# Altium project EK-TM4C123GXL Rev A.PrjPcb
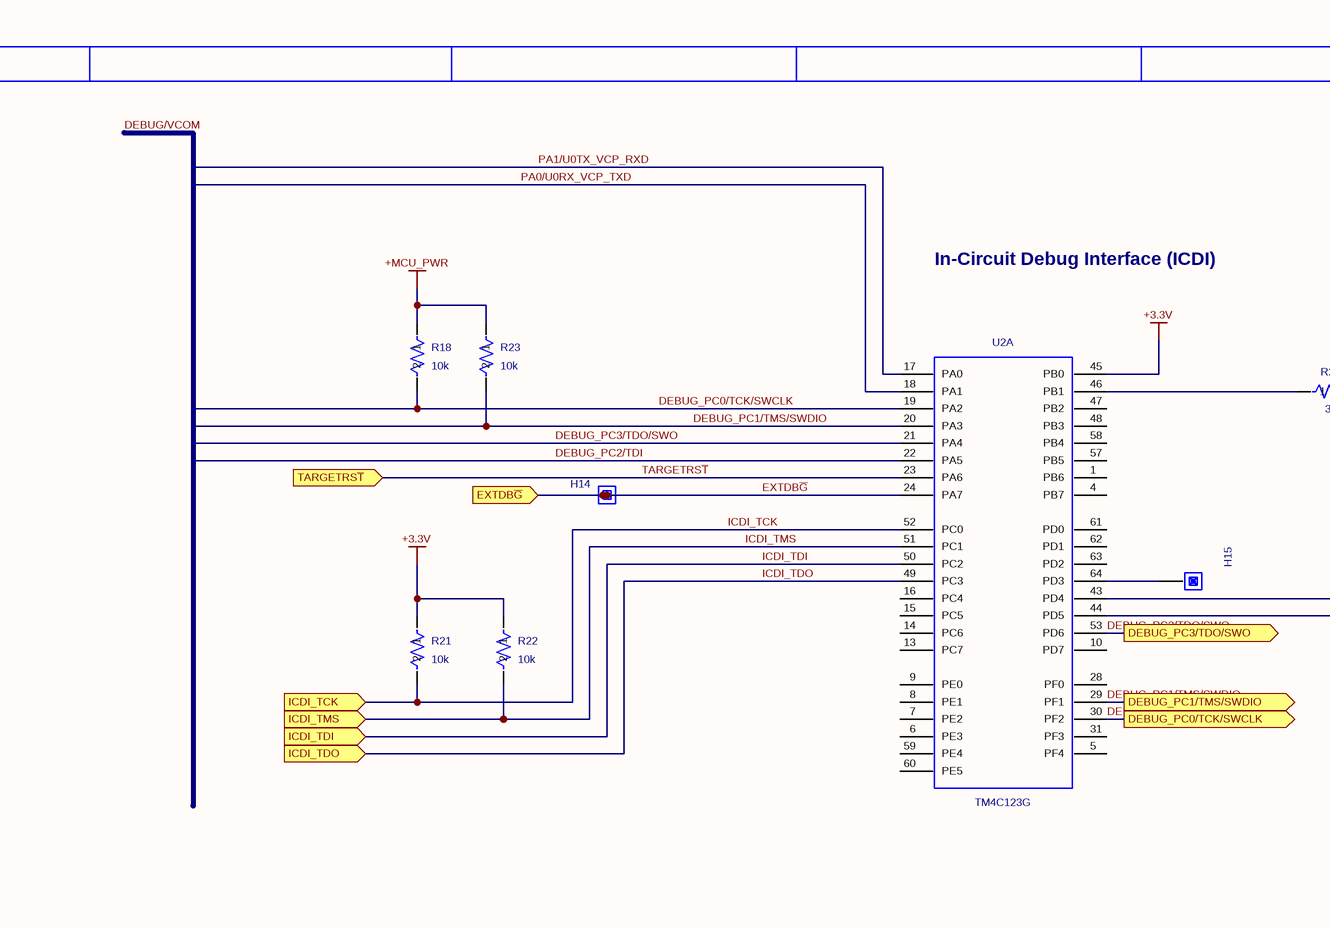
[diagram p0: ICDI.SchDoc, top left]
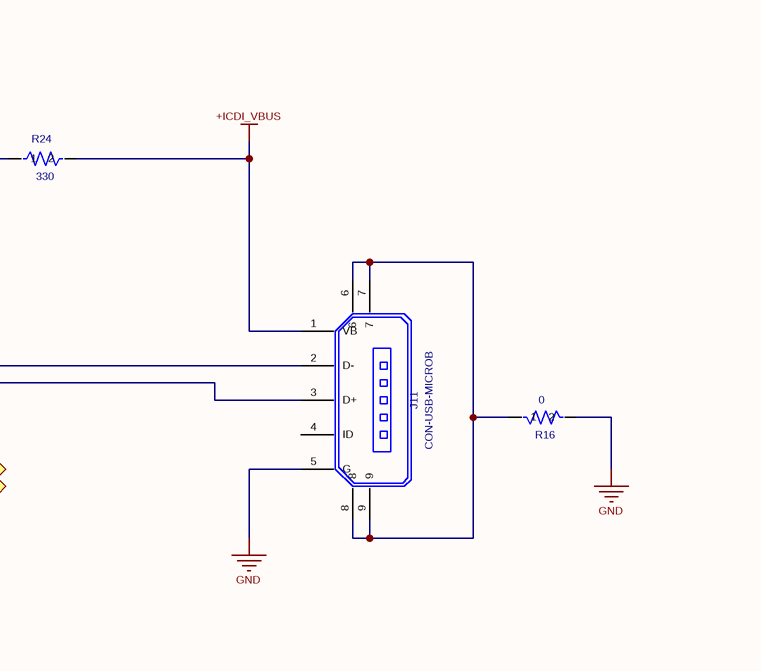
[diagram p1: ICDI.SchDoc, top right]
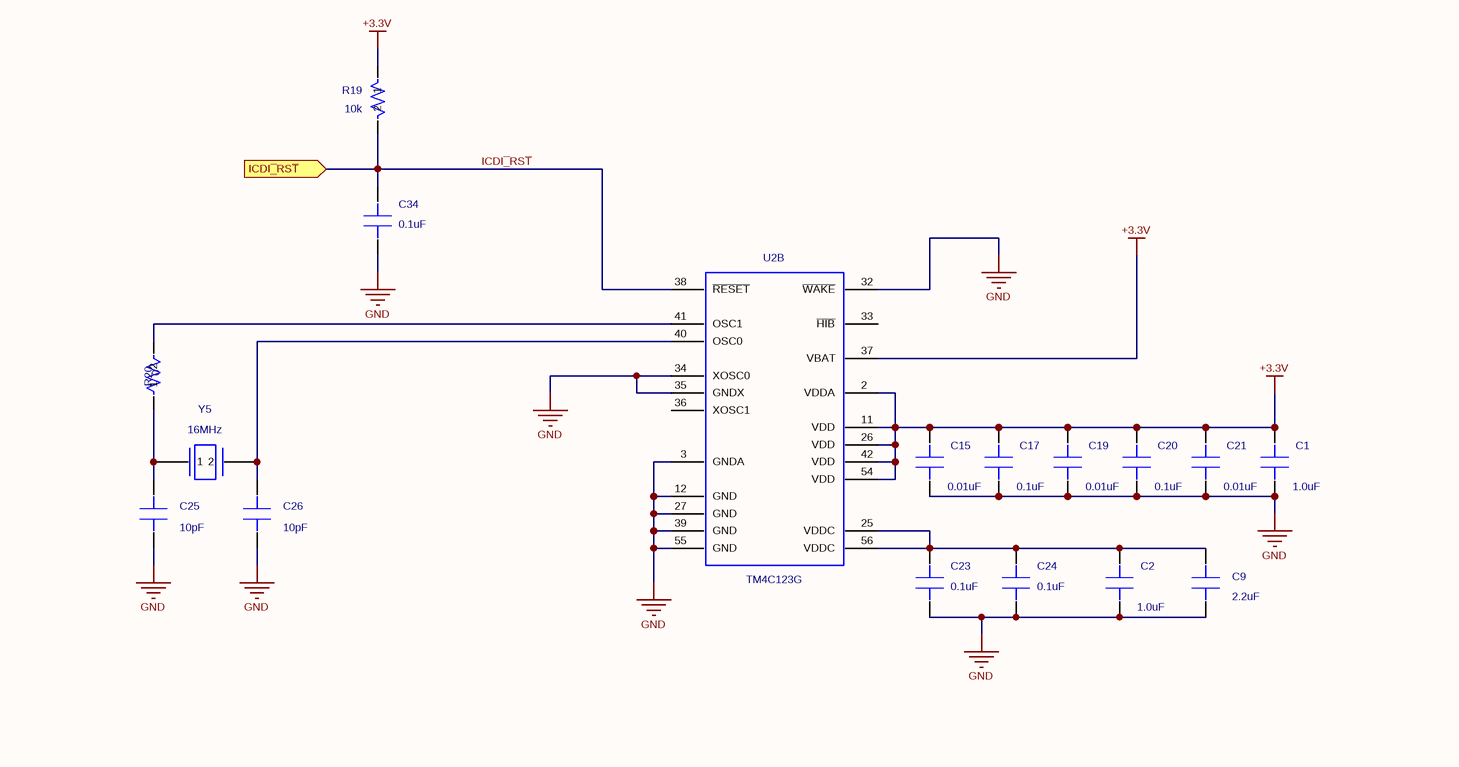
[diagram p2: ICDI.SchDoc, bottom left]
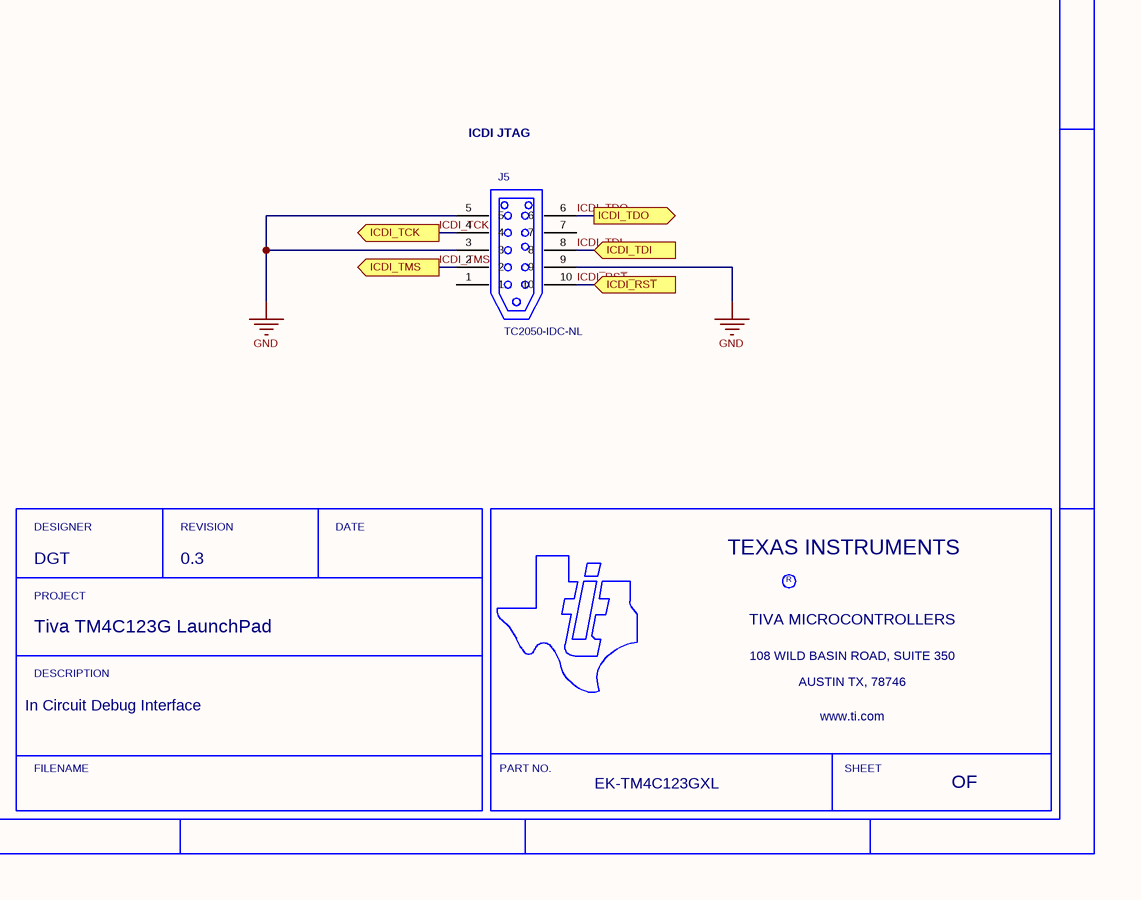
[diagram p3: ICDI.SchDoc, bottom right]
3 sheets, 107 parts. Net scope: flat (ports and power ports of the same name join across sheets).
Board files: EK-TM4C123GXL Rev A_pcb.PcbDoc, PCB4.PcbDoc
Sheets:
  ICDI.SchDoc
  IO.SchDoc
  POWER.SchDoc

## Sheet ICDI.SchDoc
size 431 x 279 mm

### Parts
C1  value 1.0uF  [CAPC0402N]  (hidden comment: CAPC0402)
C2  value 1.0uF  [CAPC0402N]  (hidden comment: CAPC0402)
C9  value 2.2uF  [CAPC0603N]  (hidden comment: CAPC0603)
C15  value 0.01uF  [CAPC0402N]  (hidden comment: CAPC0402)
C17  value 0.1uF  [CAPC0402N]  (hidden comment: CAPC0402)
C19  value 0.01uF  [CAPC0402N]  (hidden comment: CAPC0402)
C20  value 0.1uF  [CAPC0402N]  (hidden comment: CAPC0402)
C21  value 0.01uF  [CAPC0402N]  (hidden comment: CAPC0402)
C23  value 0.1uF  [CAPC0402N]  (hidden comment: CAPC0402)
C24  value 0.1uF  [CAPC0402N]  (hidden comment: CAPC0402)
C25  value 10pF  [CAPC0402N]  (hidden comment: CAPC0402)
C26  value 10pF  [CAPC0402N]  (hidden comment: CAPC0402)
C34  value 0.1uF  [CAPC0402N]  (hidden comment: CAPC0402)
H14  (no value)
H15  (no value)  [PAD70H39]
J5  TC2050-IDC-NL  [TC2050-IDC-NL]
J11  CON-USB-MICROB  [CON-USB-MICRO-S]
R16  value 0  [RESC0603N]  (hidden comment: RESC0603)
R18  value 10k  [RESC0402N]  (hidden comment: RESC0402)
R19  value 10k  [RESC0402N]  (hidden comment: RESC0402)
R20  value 0  [RESC0603N]  (hidden comment: RESC0603)
R21  value 10k  [RESC0402N]  (hidden comment: RESC0402)
R22  value 10k  [RESC0402N]  (hidden comment: RESC0402)
R23  value 10k  [RESC0402N]  (hidden comment: RESC0402)
R24  value 330  [RESC0402N]  (hidden comment: RESC0402)
U2  TM4C123G  [QFP50P1200X1200X160-64N]  (parts A,B of 2)
Y5  value 16MHz  [XTAL-NX5032GA]  (hidden comment: XTAL-NX5032GA)

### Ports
DEBUG_PC0/TCK/SWCLK, DEBUG_PC1/TMS/SWDIO, DEBUG_PC3/TDO/SWO, EXTDB~{G}, ICDI_TCK, ICDI_TCK (out), ICDI_TDI, ICDI_TDI (in), ICDI_TDO, ICDI_TMS, ICDI_TMS (out), ICDI~{_}RS~{T}, ICDI~{_}RS~{T} (in), TARGETRS~{T}

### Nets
+3.3V: C1.1 C15.1 C17.1 C19.1 C20.1 C21.1 R19.1 R21.1 R22.1 U2.2(VDDA) U2.11(VDD) U2.26(VDD) U2.37(VBAT) U2.42(VDD) U2.45(PB0) U2.54(VDD)
+ICDI_VBUS: J11.1(VB) R24.2
+MCU_PWR: R18.1 R23.1
GND: C1.2 C2.2 C9.2 C15.2 C17.2 C19.2 C20.2 C21.2 C23.2 C24.2 C25.2 C26.2 C34.2 J5.3 J5.5 J5.9 J11.5(G) R16.2 U2.3(GNDA) U2.12(GND) U2.27(GND) U2.32(~{WAKE}) U2.34(XOSC0) U2.35(GNDX) U2.39(GND) U2.55(GND)
EXTDB~{G}: H14.1 U2.24(PA7) ; port EXTDB~{G}
TARGETRS~{T}: U2.23(PA6) ; port TARGETRS~{T}
DEBUG_PC0/TCK/SWCLK: R18.2 U2.19(PA2) U2.30(PF2) ; port DEBUG_PC0/TCK/SWCLK
DEBUG_PC1/TMS/SWDIO: R23.2 U2.20(PA3) U2.29(PF1) ; port DEBUG_PC1/TMS/SWDIO
DEBUG_PC2/TDI: U2.22(PA5)
DEBUG_PC3/TDO/SWO: U2.21(PA4) U2.53(PD6) ; port DEBUG_PC3/TDO/SWO
ICDI~{_}RS~{T}: C34.1 J5.10 R19.2 U2.38(~{RESET}) ; port ICDI~{_}RS~{T}
ICDI_TCK: J5.4 R21.2 U2.52(PC0) ; port ICDI_TCK
ICDI_TDI: J5.8 U2.50(PC2) ; port ICDI_TDI
ICDI_TDO: J5.6 U2.49(PC3) ; port ICDI_TDO
ICDI_TMS: J5.2 R22.2 U2.51(PC1) ; port ICDI_TMS
PA0/U0RX_VCP_TXD: U2.18(PA1)
PA1/U0TX_VCP_RXD: U2.17(PA0)
NetC2_1: C2.1 C9.1 C23.1 C24.1 U2.25(VDDC) U2.56(VDDC)
NetC25_1: C25.1 R20.1 Y5.1
NetC26_1: C26.1 U2.40(OSC0) Y5.2
NetH15_1: H15.1 U2.64(PD3)
NetJ11_2: J11.2(D-) U2.43(PD4)
NetJ11_3: J11.3(D+) U2.44(PD5)
NetJ11_6: J11.6 J11.7 J11.8 J11.9 R16.1
NetR20_2: R20.2 U2.41(OSC1)
NetR24_1: R24.1 U2.46(PB1)

Not connected (* = marked no-connect by the designer): J5 1 7; J11 4(ID); U2 1(PB6) 4(PB7) 5(PF4) 6(PE3) 7(PE2) 8(PE1) 9(PE0) 10(PD7) 13(PC7) 14(PC6) 15(PC5) 16(PC4) 28(PF0) 31(PF3) 33(~{HIB}) 36(XOSC1) 47(PB2) 48(PB3) 57(PB5) 58(PB4) 59(PE4) 60(PE5) 61(PD0) 62(PD1) 63(PD2)

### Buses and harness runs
bus DEBUG/VCOM

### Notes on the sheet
- In-Circuit Debug Interface (ICDI)
- ICDI JTAG
- DGT
- DESIGNER
- 0.3
- REVISION
- DATE
- R
- TEXAS INSTRUMENTS
- Tiva TM4C123G LaunchPad
- PROJECT
- TIVA MICROCONTROLLERS
- 108 WILD BASIN ROAD, SUITE 350
- In Circuit Debug Interface
- DESCRIPTION
- www.ti.com
- AUSTIN TX, 78746
- FILENAME
- PART NO.
- EK-TM4C123GXL
- SHEET
- OF

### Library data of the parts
C1 C2 = CAPC0402: SURFACE MOUNT CAPACITOR 0402; Manufacturer #1: IPC SM-782 STD.; Sim.Analog.Order: Model$; GNUM: G10-C0402-C105-GBB
C9 = CAPC0603: SURFACE MOUNT CAPACITOR 0.031 X 0.061 INCHES; Manufacturer #1: IPC SM-782 STD.; Sim.Analog.Order: Model$; GNUM: G10-C0603-C225-HBB
C15 C19 C21 = CAPC0402: SURFACE MOUNT CAPACITOR 0402; Manufacturer #1: IPC SM-782 STD.; Sim.Analog.Order: Model$; GNUM: G10-C0402-C103-BBA
C17 C20 C23 C24 = CAPC0402: SURFACE MOUNT CAPACITOR 0402; Manufacturer #1: IPC SM-782 STD.; Sim.Analog.Order: Model$; GNUM: G10-C0402-C104-HBA
C25 C26 = CAPC0402: SURFACE MOUNT CAPACITOR 0402; Manufacturer #1: IPC SM-782 STD.; Sim.Analog.Order: Model$; GNUM: C10-C0402-C100-AAC
C34 = CAPC0402: OMIT; Manufacturer #1: IPC SM-782 STD.; Sim.Analog.Order: Model$; GNUM: G10-C0402-C104-HBA
H14 = HDR-INLINE: POPOP: OMIT
H15 = HDR-ENDLINE: POPOP: OMIT
J5 = TC2050-IDC-NL: POPOP: OMIT
J11 = CON-USB-MICROB: Connector, USB micro AB Receptacle SMT; Part Number: ZX62-B-5PA; Manufacturer #1: Hirose; GNUM: G20-USBM-SMMB-AAA
R16 = RESC0603: GNUM: G11-R0603-R000-AAA
R18 R19 R21-R23 = RESC0402: Resistor,Chip;1.00mm L X 0.5mm W X 0.35mm H; Manufacturer #1: Generic; Part Number: TBD; Also Known As: 0402; PCBL.Component: CHP;RESC;1500;1700;150;400;700;950;600; PCBL.Process: F;N;50;50;200;100;200;250;350;-50;0; Tolerance: 5%; GNUM: G11-R0402-1002-AAA
R20 = RESC0603: Resistor,Chip;1.60mm L X 0.83mm W X 0.60mm H; Manufacturer #1: Generic; Part Number: TBD; GNUM: G11-R0603-R000-AAA; Also Known As: 0603; Geometry.Height: 0.6mm; PCBL.Component: CHP;RESC;1500;1700;150;400;700;950;600; PCBL.Process: F;N;50;50;200;100;200;250;350;-50;0
R24 = RESC0402: Resistor,Chip;1.00mm L X 0.5mm W X 0.35mm H; Manufacturer #1: Generic; Part Number: TBD; Also Known As: 0402; PCBL.Component: CHP;RESC;1500;1700;150;400;700;950;600; PCBL.Process: F;N;50;50;200;100;200;250;350;-50;0; Tolerance: 5%; GNUM: G11-R0402-3300-AAA; POPOP: OMIT
U2 = TM4C123G: GNUM: G50-QFP64-F120-EGC
Y5 = XTAL-NX5032GA: Crystal, 16.00MHz 5.0x3.2mm SMT; Manufacturer #1: tbd; Part Number: NX5032GA-16.000000MHZ; GNUM: G15-5X3P2-1606-AAA

## Sheet IO.SchDoc
size 431 x 279 mm
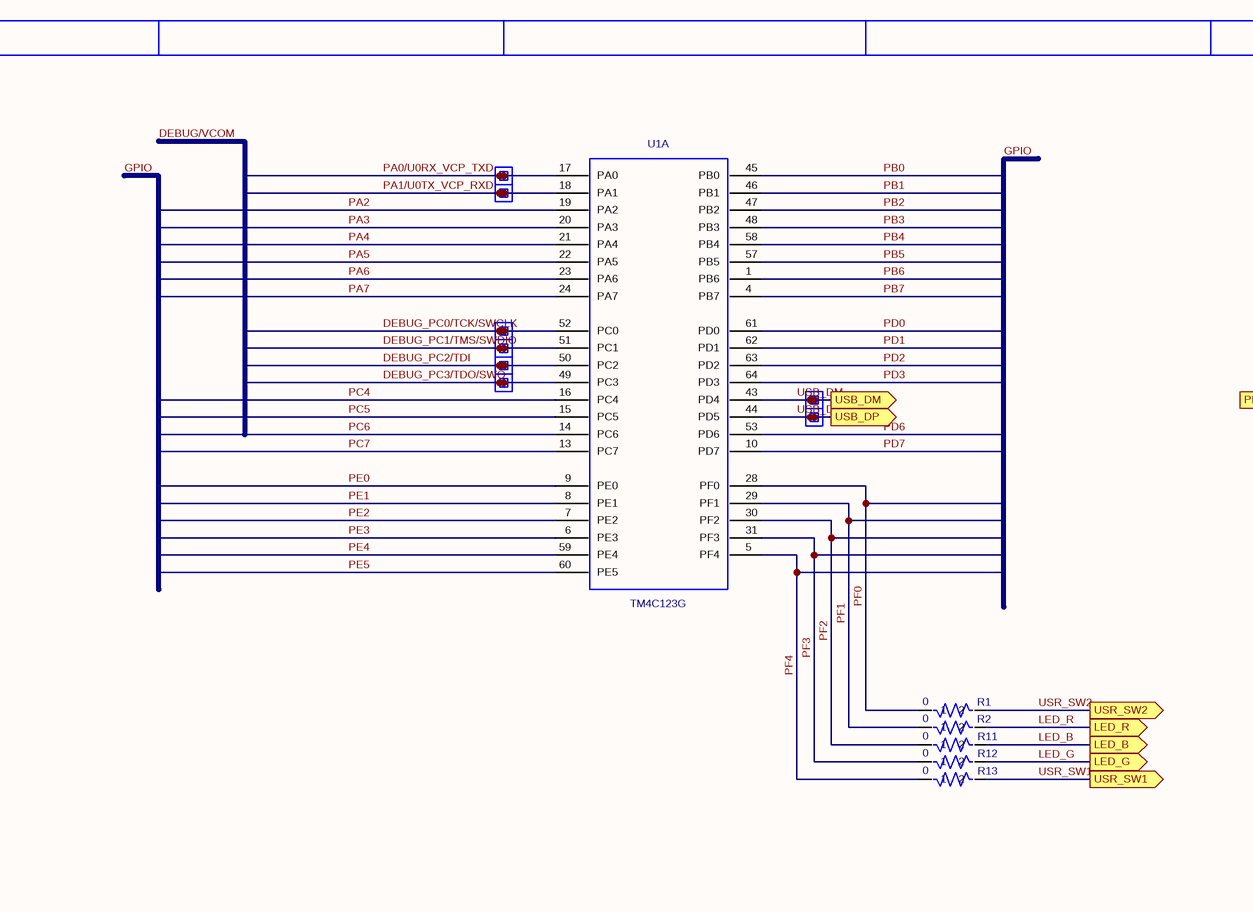
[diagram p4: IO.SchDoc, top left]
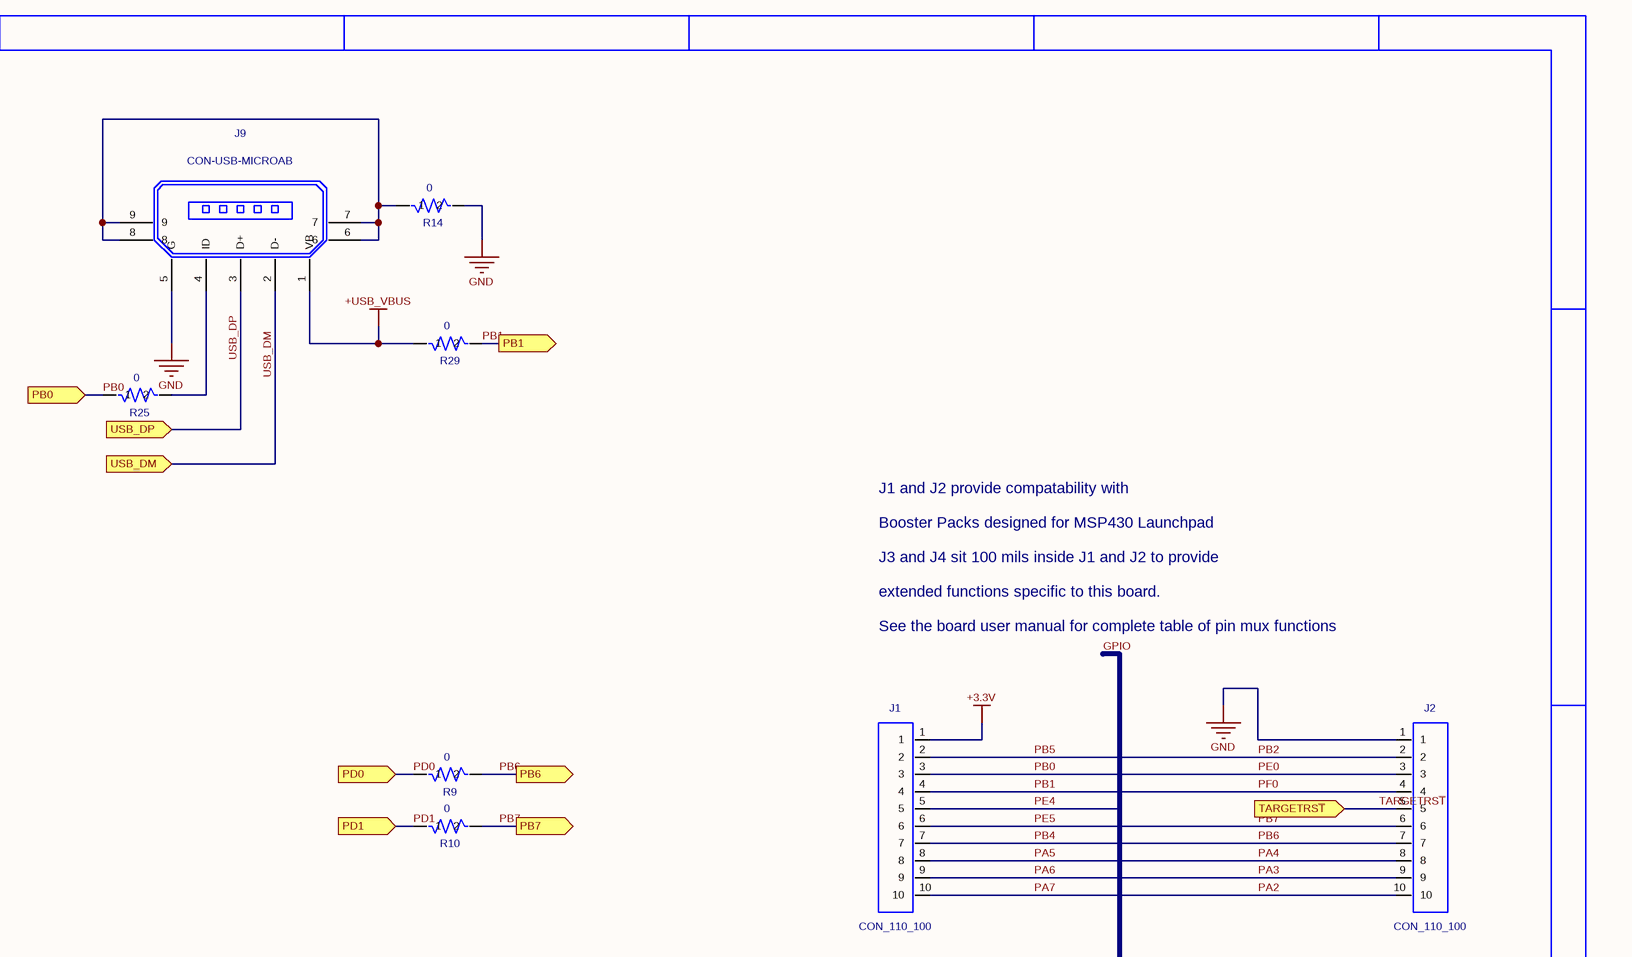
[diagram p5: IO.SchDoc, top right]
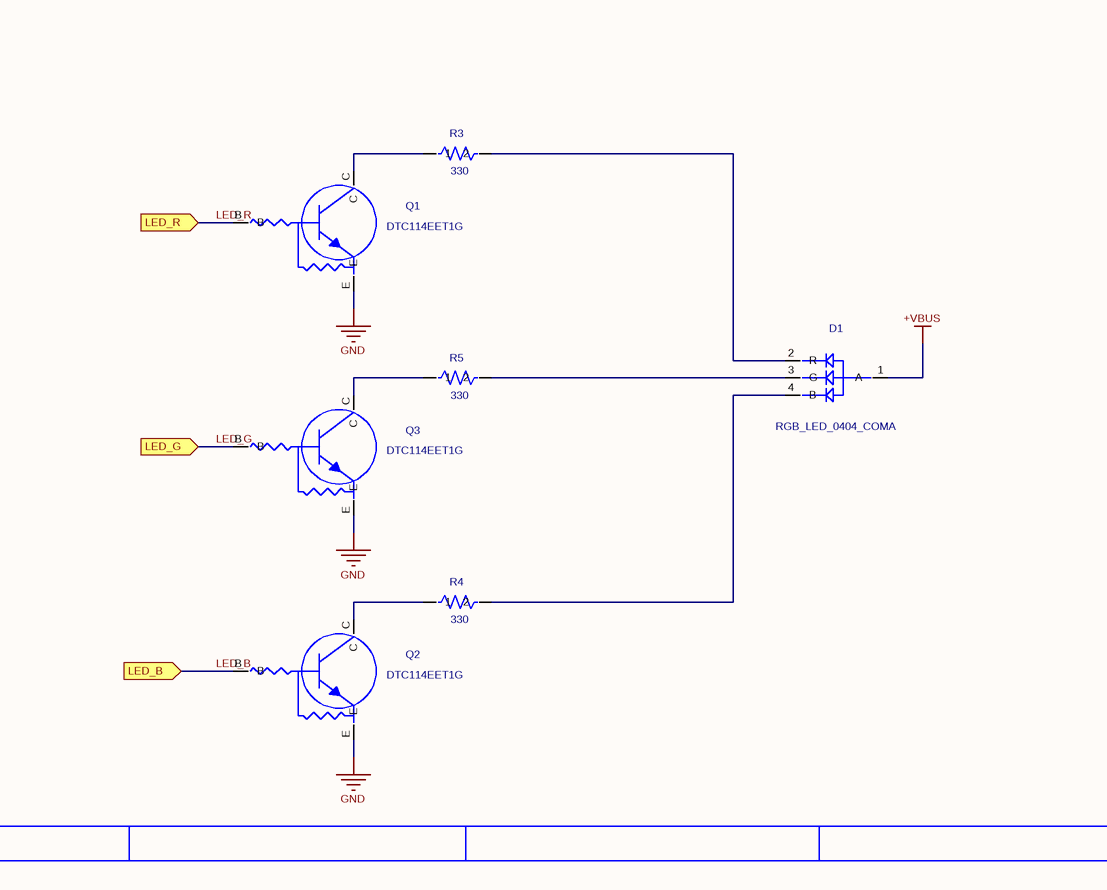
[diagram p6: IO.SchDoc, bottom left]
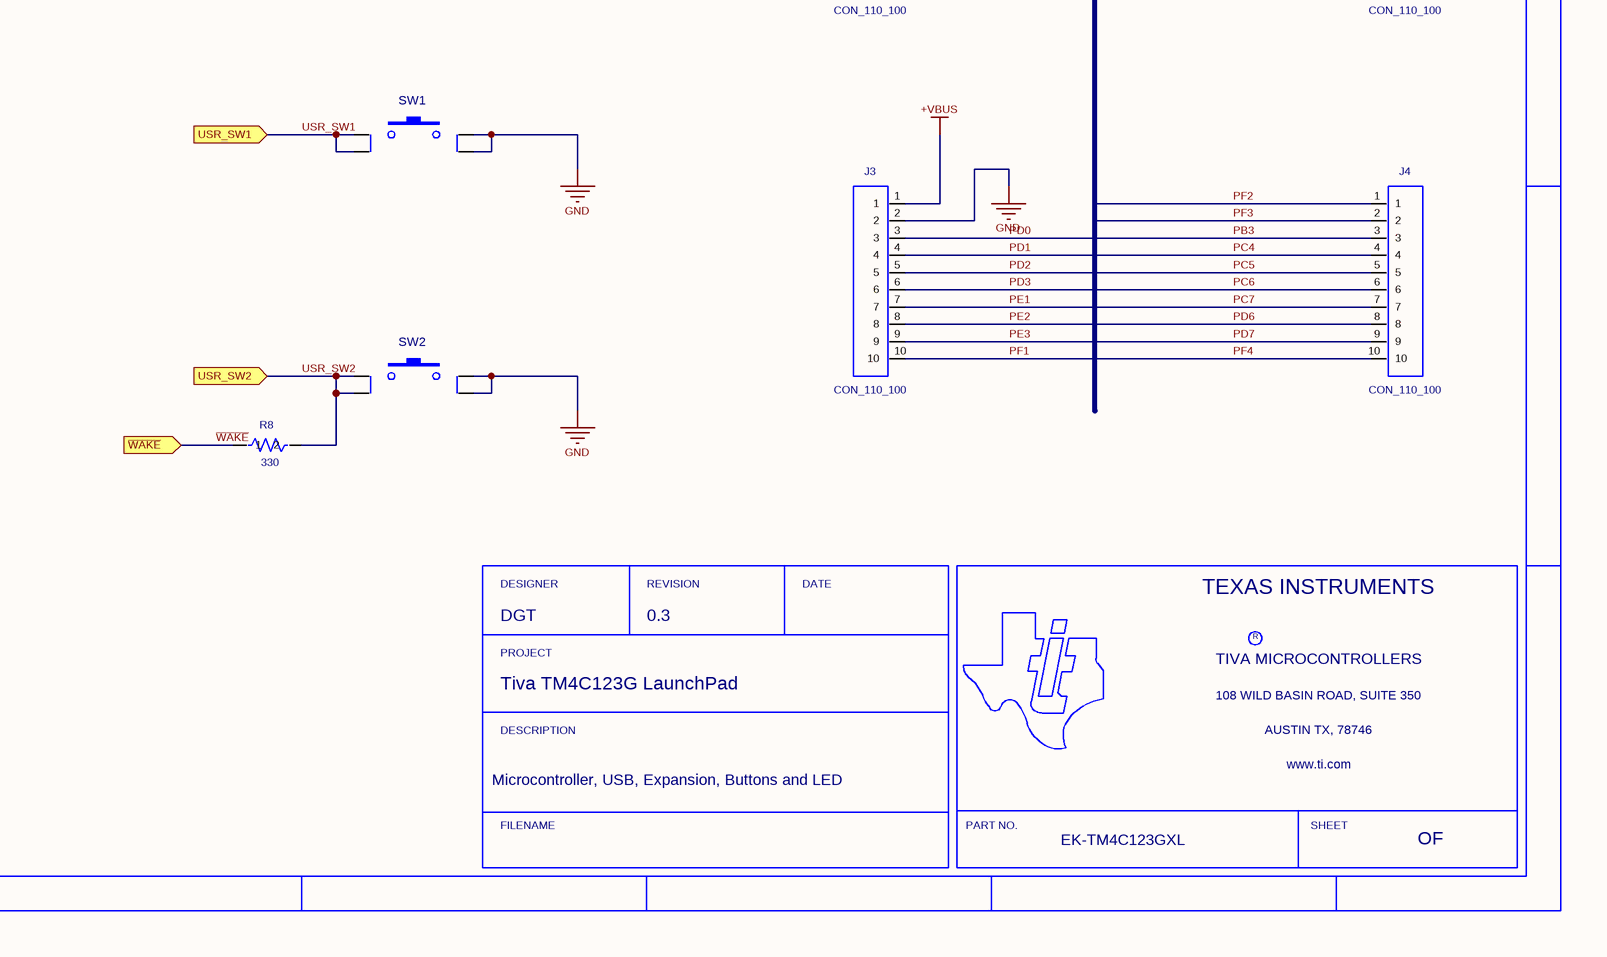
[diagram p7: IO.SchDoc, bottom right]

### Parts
D1  RGB_LED_0404_COMA  [0404_QUAD]
H3  (no value)
H4  (no value)
H5  (no value)
H6  (no value)
H7  (no value)
H8  (no value)
H9  (no value)
H91  (no value)
J1  CON_110_100  [TSW-110-100]
J2  CON_110_100  [TSW-110-100]
J3  CON_110_100  [TSW-110-100]
J4  CON_110_100  [TSW-110-100]
J9  CON-USB-MICROAB  [CON-USB-MICRO-S]
Q1  DTC114EET1G  [SC-75/SOT-416]
Q2  DTC114EET1G  [SC-75/SOT-416]
Q3  DTC114EET1G  [SC-75/SOT-416]
R1  value 0  [RESC0603N]  (hidden comment: RESC0603)
R2  value 0  [RESC0603N]  (hidden comment: RESC0603)
R3  value 330  [RESC0402N]  (hidden comment: RESC0402)
R4  value 330  [RESC0402N]  (hidden comment: RESC0402)
R5  value 330  [RESC0402N]  (hidden comment: RESC0402)
R8  value 330  [RESC0402N]  (hidden comment: RESC0402)
R9  value 0  [RESC0603N]  (hidden comment: RESC0603)
R10  value 0  [RESC0603N]  (hidden comment: RESC0603)
R11  value 0  [RESC0603N]  (hidden comment: RESC0603)
R12  value 0  [RESC0603N]  (hidden comment: RESC0603)
R13  value 0  [RESC0603N]  (hidden comment: RESC0603)
R14  value 0  [RESC0603N]  (hidden comment: RESC0603)
R25  value 0  [RESC0603N]  (hidden comment: RESC0603)
R29  value 0  [RESC0603N]  (hidden comment: RESC0603)
SW1  SW-EVQQ2  [SW-EVQQ2]  (value not drawn)
SW2  SW-EVQQ2  [SW-EVQQ2]  (value not drawn)
U1  TM4C123G  [QFP50P1200X1200X160-64N]  (part A of 2)

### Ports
LED_B, LED_G, LED_R, PB0, PB1, PB6, PB7, PD0, PD1, TARGETRS~{T}, USB_DM, USB_DP, USR_SW1, USR_SW2, ~{WAKE}

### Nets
+3.3V: J1.1
+USB_VBUS: J9.1(VB) R29.1
+VBUS: D1.1(A) J3.1
GND: J2.1 J3.2 J9.5(G) Q1.E Q2.E Q3.E R14.2 SW1.2 SW1.4 SW2.2 SW2.4
TARGETRS~{T}: J2.5 ; port TARGETRS~{T}
~{WAKE}: R8.1 ; port ~{WAKE}
DEBUG_PC0/TCK/SWCLK: H91.1 U1.52(PC0)
DEBUG_PC1/TMS/SWDIO: H3.1 U1.51(PC1)
DEBUG_PC2/TDI: H4.1 U1.50(PC2)
DEBUG_PC3/TDO/SWO: H5.1 U1.49(PC3)
LED_B: Q2.B R11.2 ; port LED_B
LED_G: Q3.B R12.2 ; port LED_G
LED_R: Q1.B R2.2 ; port LED_R
PA0/U0RX_VCP_TXD: H6.1 U1.17(PA0)
PA1/U0TX_VCP_RXD: H7.1 U1.18(PA1)
PA2: J1.10 J2.10 U1.19(PA2) U1.24(PA7)  [also labelled PA7]
PA3: J1.9 J2.9 U1.20(PA3) U1.23(PA6)  [also labelled PA6]
PA4: J1.8 J2.8 U1.21(PA4) U1.22(PA5)  [also labelled PA5]
PB0: J1.3 J2.3 R25.1 U1.9(PE0) U1.45(PB0) ; port PB0  [also labelled PE0]
PB1: J1.4 J2.4 R1.1 R29.2 U1.28(PF0) U1.46(PB1) ; port PB1  [also labelled PF0]
PB2: J1.2 J2.2 U1.47(PB2) U1.57(PB5)  [also labelled PB5]
PB3: J3.3 J4.3 R9.1 U1.48(PB3) U1.61(PD0) ; port PD0  [also labelled PD0]
PB4: J1.7 J2.7 R9.2 U1.1(PB6) U1.58(PB4) ; port PB6  [also labelled PB6]
PB7: J1.6 J2.6 R10.2 U1.4(PB7) U1.60(PE5) ; port PB7  [also labelled PE5]
PC4: J3.4 J4.4 R10.1 U1.16(PC4) U1.62(PD1) ; port PD1  [also labelled PD1]
PC5: J3.5 J4.5 U1.15(PC5) U1.63(PD2)  [also labelled PD2]
PC6: J3.6 J4.6 U1.14(PC6) U1.64(PD3)  [also labelled PD3]
PC7: J3.7 J4.7 U1.8(PE1) U1.13(PC7)  [also labelled PE1]
PD6: J3.8 J4.8 U1.7(PE2) U1.53(PD6)  [also labelled PE2]
PD7: J3.9 J4.9 U1.6(PE3) U1.10(PD7)  [also labelled PE3]
PE4: J1.5 U1.59(PE4)
PF1: J3.10 J4.10 R2.1 R13.1 U1.5(PF4) U1.29(PF1)  [also labelled PF4]
PF2: J4.1 R11.1 U1.30(PF2)
PF3: J4.2 R12.1 U1.31(PF3)
USB_DM: H8.1 J9.2(D-) U1.43(PD4) ; port USB_DM
USB_DP: H9.1 J9.3(D+) U1.44(PD5) ; port USB_DP
USR_SW1: R13.2 SW1.1 SW1.3 ; port USR_SW1
USR_SW2: R1.2 R8.2 SW2.1 SW2.3 ; port USR_SW2
NetD1_2: D1.2(R) R3.2
NetD1_3: D1.3(G) R5.2
NetD1_4: D1.4(B) R4.2
NetJ9_4: J9.4(ID) R25.2
NetJ9_6: J9.6 J9.7 J9.8 J9.9 R14.1
NetQ1_C: Q1.C R3.1
NetQ2_C: Q2.C R4.1
NetQ3_C: Q3.C R5.1

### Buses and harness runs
bus DEBUG/VCOM
bus GPIO

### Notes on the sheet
- J1 and J2 provide compatability with
- Booster Packs designed for MSP430 Launchpad
- J3 and J4 sit 100 mils inside J1 and J2 to provide
- extended functions specific to this board.
- See the board user manual for complete table of pin mux functions
- DGT
- DESIGNER
- 0.3
- REVISION
- DATE
- R
- TEXAS INSTRUMENTS
- Tiva TM4C123G LaunchPad
- PROJECT
- 108 WILD BASIN ROAD, SUITE 350
- TIVA MICROCONTROLLERS
- Microcontroller, USB, Expansion, Buttons and LED
- DESCRIPTION
- www.ti.com
- AUSTIN TX, 78746
- FILENAME
- PART NO.
- EK-TM4C123GXL
- SHEET
- OF

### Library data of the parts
D1 = RGB_LED_0404_COMA: GNUM: G14-D0404-RGB3-AAA
H3-H9 H91 = HDR-INLINE: POPOP: OMIT
J1 J3 = CON_110_100: PIN1_X: 0.3; PIN1_Y: 1.4; Geometry.Height: 50.00mil; GNUM: G22-THSTK-2X10-BAC
J2 = CON_110_100: PIN1_X: 2.1; PIN1_Y: 1.4; Geometry.Height: 50.00mil; GNUM: G22-SMHOR-210P-BAB
J4 = CON_110_100: PIN1_X: 0.3; PIN1_Y: 1.4; Geometry.Height: 50.00mil; GNUM: G22-SMHOR-210P-BAB
J9 = CON-USB-MICROAB: Connector, USB micro AB Receptacle SMT; Part Number: ZX62-AB-5PA; Manufacturer #1: Hirose; GNUM: G20-USBU-SMAB-AAA
Q1-Q3 = DTC114EET1G: GENERAL PURPOSE NPN SILICON TRANSISTOR; Manufacturer #1: Diodes Inc; GNUM: G52-SC700-NPNB-AAA
R1 R2 R9-R14 = RESC0603: GNUM: G11-R0603-R000-AAA
R3-R5 R8 = RESC0402: Resistor,Chip;1.00mm L X 0.5mm W X 0.35mm H; Manufacturer #1: Generic; Part Number: TBD; Also Known As: 0402; PCBL.Component: CHP;RESC;1500;1700;150;400;700;950;600; PCBL.Process: F;N;50;50;200;100;200;250;350;-50;0; Tolerance: 5%; GNUM: G11-R0402-3300-AAA
R25 R29 = RESC0603: GNUM: G11-R0603-R000-AAA; POPOP: OMIT
SW1 SW2 = SW-EVQQ2: Switch, Tact 6mm SMT, 50gf; Manufacturer #1: Panasonic; Part Number: EVQ-Q2B02W; GNUM: G21-4P6MM-B3S1-AAA
U1 = TM4C123G: GNUM: G50-QFP64-F120-EGC

## Sheet POWER.SchDoc
size 431 x 279 mm
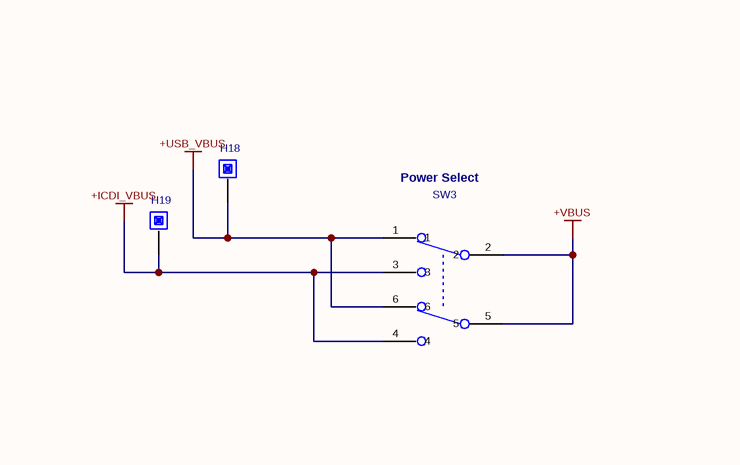
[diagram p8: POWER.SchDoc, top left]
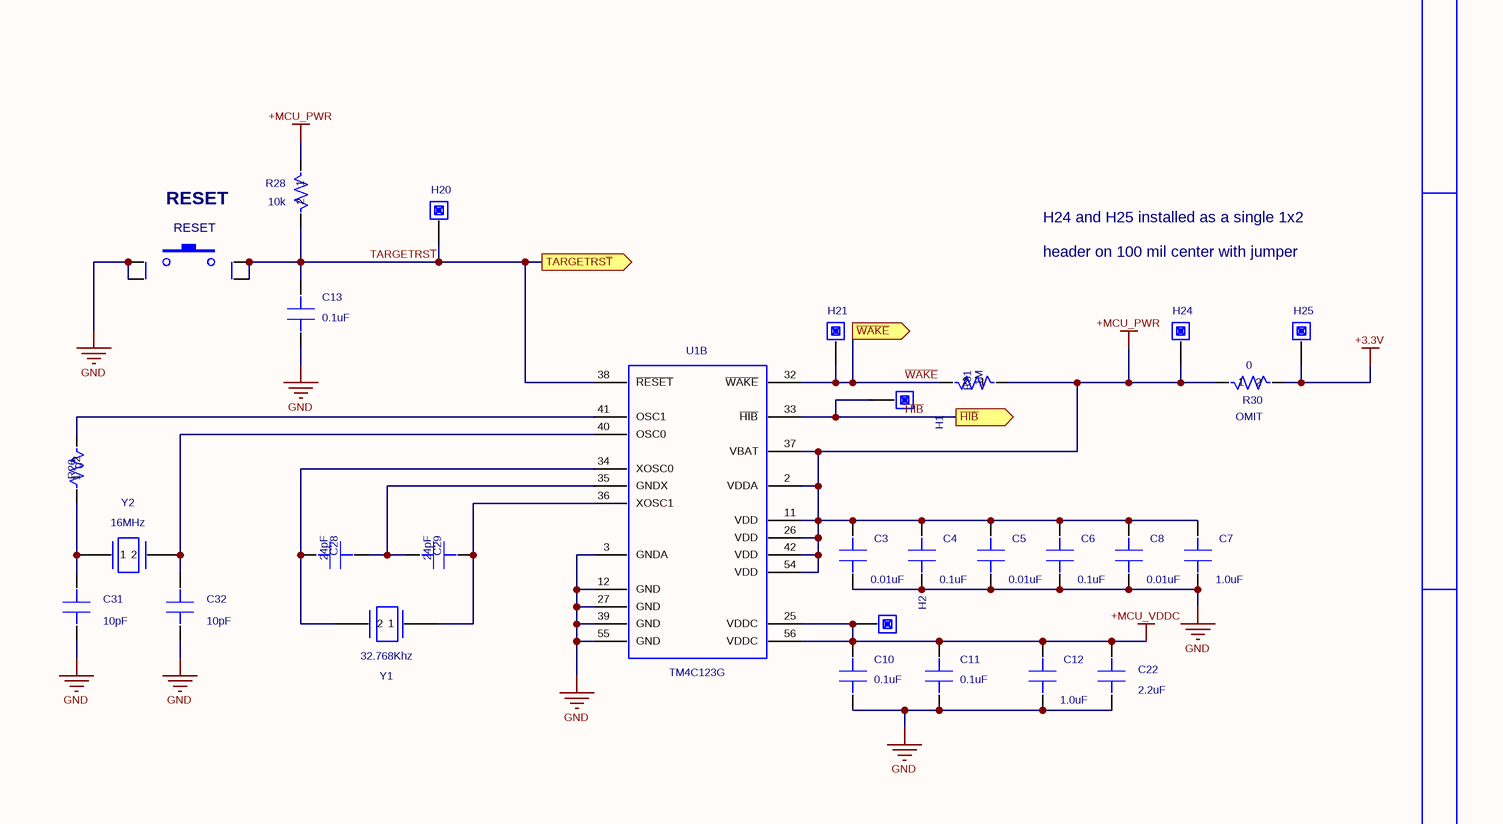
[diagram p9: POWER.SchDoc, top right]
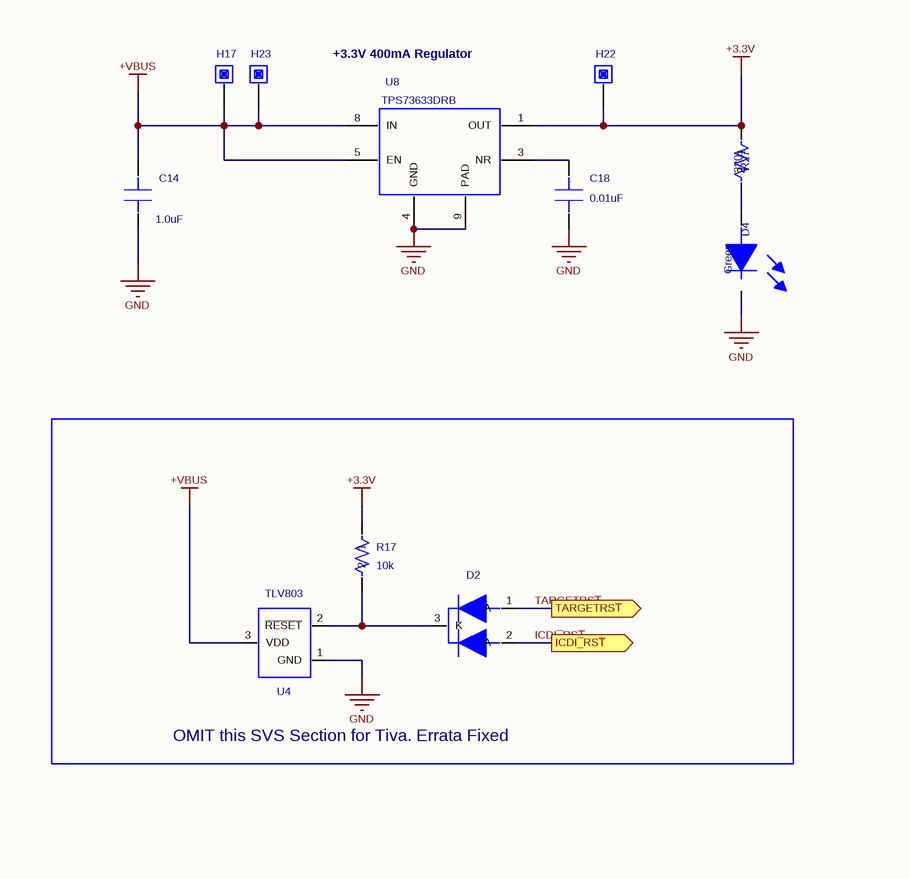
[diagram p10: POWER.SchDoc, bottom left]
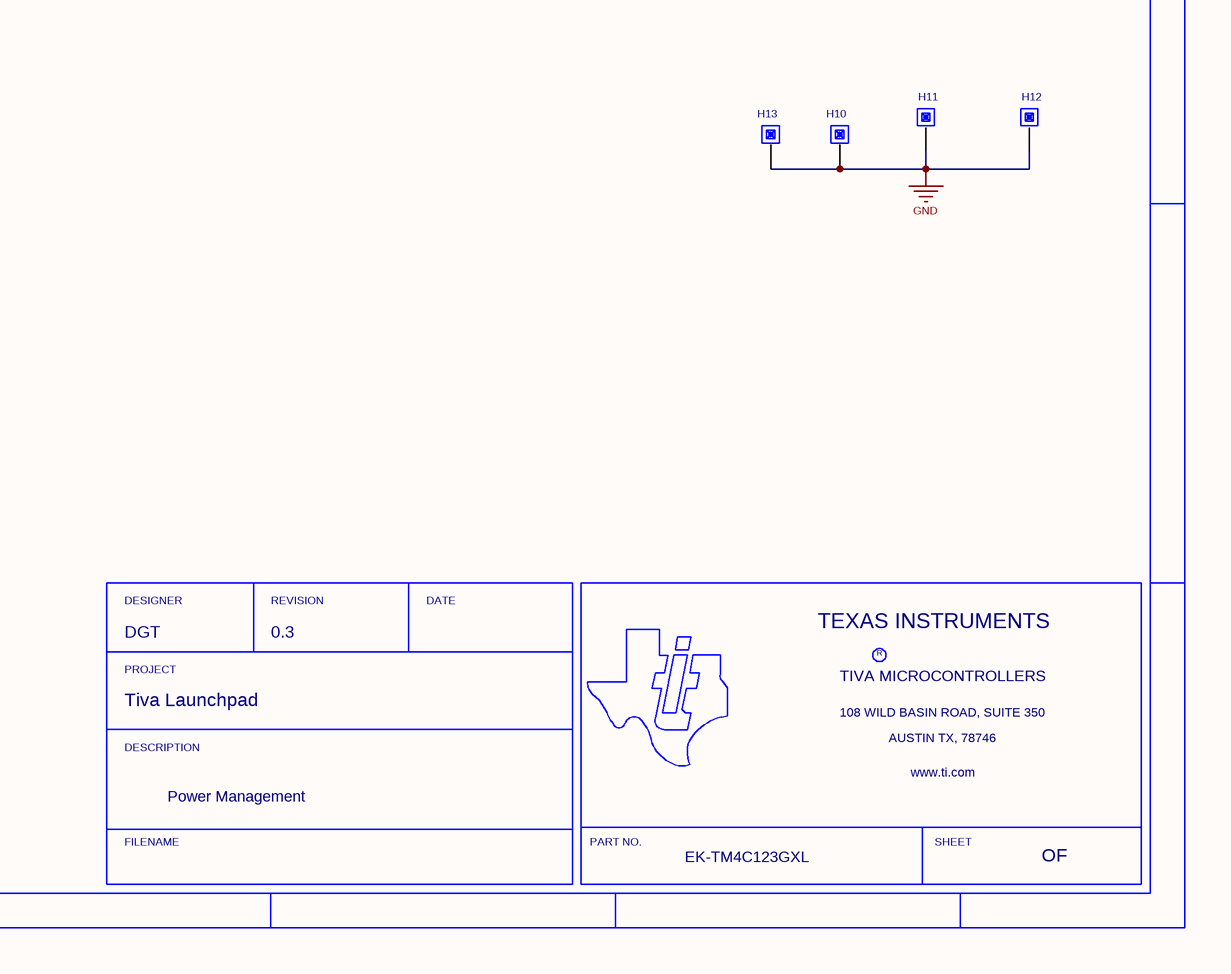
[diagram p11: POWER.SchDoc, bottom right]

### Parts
C3  value 0.01uF  [CAPC0402N]  (hidden comment: CAPC0402)
C4  value 0.1uF  [CAPC0402N]  (hidden comment: CAPC0402)
C5  value 0.01uF  [CAPC0402N]  (hidden comment: CAPC0402)
C6  value 0.1uF  [CAPC0402N]  (hidden comment: CAPC0402)
C7  value 1.0uF  [CAPC0402N]  (hidden comment: CAPC0402)
C8  value 0.01uF  [CAPC0402N]  (hidden comment: CAPC0402)
C10  value 0.1uF  [CAPC0402N]  (hidden comment: CAPC0402)
C11  value 0.1uF  [CAPC0402N]  (hidden comment: CAPC0402)
C12  value 1.0uF  [CAPC0402N]  (hidden comment: CAPC0402)
C13  value 0.1uF  [CAPC0402N]  (hidden comment: CAPC0402)
C14  value 1.0uF  [CAPC0402N]  (hidden comment: CAPC0402)
C18  value 0.01uF  [CAPC0402N]  (hidden comment: CAPC0402)
C22  value 2.2uF  [CAPC0603N]  (hidden comment: CAPC0603)
C28  value 24pF  [CAPC0402N]  (hidden comment: CAPC0402)
C29  value 24pF  [CAPC0402N]  (hidden comment: CAPC0402)
C31  value 10pF  [CAPC0402N]  (hidden comment: CAPC0402)
C32  value 10pF  [CAPC0402N]  (hidden comment: CAPC0402)
D2  DIO_BAT54_CC  [SC70-3]  (value not drawn)
D4  value Green  [DIOC0805N]  (hidden comment: LED-0805)
H1  (no value)  [PAD70H39]
H2  (no value)  [PAD70H39]
H10  (no value)  [PAD70H39]
H11  (no value)  [PAD70H39]
H12  (no value)  [PAD70H39]
H13  (no value)  [PAD70H39]
H17  (no value)  [PAD70H39]
H18  (no value)  [PAD70H39]
H19  (no value)  [PAD70H39]
H20  (no value)  [PAD70H39]
H21  (no value)  [PAD70H39]
H22  (no value)  [PAD70H39]
H23  (no value)  [PAD70H39]
H24  (no value)  [PAD70H39]
H25  (no value)  [PAD70H39]
R17  value 10k  [RESC0402N]  (hidden comment: RESC0402)
R26  value 0  [RESC0603N]  (hidden comment: RESC0603)
R27  value 330  [RESC0402N]  (hidden comment: RESC0402)
R28  value 10k  [RESC0402N]  (hidden comment: RESC0402)
R30  OMIT  value 0  [RESC0603N]
R31  value 1M  [RESC0402N]  (hidden comment: RESC0402)
RESET  SW-EVQQ2  [SW-EVQQ2]  (value not drawn)
SW3  SW_DPDT  [SW_JS202011SCQN]  (value not drawn)
U1  TM4C123G  [QFP50P1200X1200X160-64N]  (part B of 2)
U4  TLV803  [SOT23]
U8  TPS73633DRB  [TI-DRB-SON8]
Y1  value 32.768Khz  [XTAL-AB26TR]  (hidden comment: XTAL-NX5032GA)
Y2  value 16MHz  [XTAL-NX5032GA]  (hidden comment: XTAL-NX5032GA)

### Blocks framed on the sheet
OMIT this SVS Section for Tiva. Errata Fixed: D2 R17 U4

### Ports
ICDI~{_}RS~{T}, TARGETRS~{T}, ~{HIB}, ~{WAKE}

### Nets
+3.3V: H22.1 H25.1 R17.1 R27.1 R30.2 U8.1(OUT)
+ICDI_VBUS: H19.1 SW3.3 SW3.4
+MCU_PWR: C3.1 C4.1 C5.1 C6.1 C7.1 C8.1 H24.1 R28.1 R30.1 R31.1 U1.2(VDDA) U1.11(VDD) U1.26(VDD) U1.37(VBAT) U1.42(VDD) U1.54(VDD)
+MCU_VDDC: C10.1 C11.1 C12.1 C22.1 H2.1 U1.25(VDDC) U1.56(VDDC)
+USB_VBUS: H18.1 SW3.1 SW3.6
+VBUS: C14.1 H17.1 H23.1 SW3.2 SW3.5 U4.3(VDD) U8.5(EN) U8.8(IN)
GND: C3.2 C4.2 C5.2 C6.2 C7.2 C8.2 C10.2 C11.2 C12.2 C13.2 C14.2 C18.2 C22.2 C31.2 C32.2 D4.1 H10.1 H11.1 H12.1 H13.1 RESET.1 RESET.3 U1.3(GNDA) U1.12(GND) U1.27(GND) U1.39(GND) U1.55(GND) U4.1(GND) U8.4(GND) U8.9(PAD)
~{HIB}: H1.1 U1.33(~{HIB}) ; port ~{HIB}
TARGETRS~{T}: C13.1 D2.1(A) H20.1 R28.2 RESET.2 RESET.4 U1.38(~{RESET}) ; port TARGETRS~{T}
~{WAKE}: H21.1 R31.2 U1.32(~{WAKE}) ; port ~{WAKE}
ICDI~{_}RS~{T}: D2.2(A) ; port ICDI~{_}RS~{T}
NetC18_1: C18.1 U8.3(NR)
NetC28_1: C28.1 U1.34(XOSC0) Y1.2
NetC28_2: C28.2 C29.1 U1.35(GNDX)
NetC29_2: C29.2 U1.36(XOSC1) Y1.1
NetC31_1: C31.1 R26.1 Y2.1
NetC32_1: C32.1 U1.40(OSC0) Y2.2
NetD2_3: D2.3(K) R17.2 U4.2(~{RESET})
NetD4_2: D4.2 R27.2
NetR26_2: R26.2 U1.41(OSC1)

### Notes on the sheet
- RESET
- H24 and H25 installed as a single 1x2
- (near SW3) Power Select
- header on 100 mil center with jumper
- +3.3V 400mA Regulator
- DGT
- DESIGNER
- 0.3
- REVISION
- DATE
- R
- TEXAS INSTRUMENTS
- Tiva Launchpad
- PROJECT
- TIVA MICROCONTROLLERS
- 108 WILD BASIN ROAD, SUITE 350
- DESCRIPTION
- Power Management
- www.ti.com
- AUSTIN TX, 78746
- FILENAME
- PART NO.
- EK-TM4C123GXL
- SHEET
- OF

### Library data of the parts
C3 C5 C8 C18 = CAPC0402: as C15 on sheet ICDI
C4 C6 C10 C11 = CAPC0402: as C17 on sheet ICDI
C7 C12 = CAPC0402: as C1 on sheet ICDI
C13 = CAPC0402: as C34 on sheet ICDI
C14 = CAPC0402: SURFACE MOUNT CAPACITOR 0402; Manufacturer #1: Johanson Dielectric; Sim.Analog.Order: Model$; GNUM: G10-C0402-C105-GBB
C22 = CAPC0603: as C9 on sheet ICDI
C28 C29 = CAPC0402: SURFACE MOUNT CAPACITOR 0402; Manufacturer #1: IPC SM-782 STD.; GNUM: C10-C0402-C240-AAC; Sim.Analog.Order: Model$
C31 C32 = CAPC0402: as C25 on sheet ICDI
D2 = DIO_BAT54_CC: GNUM: G14-SC700-BAS7-BAA; POPOP: OMIT
D4 = LED-0805: SMT LED IN 0805 PACK; Manufacturer #1: LITE-ON; Part Number: LTST-C170xKT; GNUM: G14-D0805-GR00-AAA
H1 H2 H10-H13 H17-H23 = HDR-ENDLINE: POPOP: OMIT
H24 = HDR-ENDLINE: GNUM: G22-THVEU-002P-AAA
H25 = HDR-ENDLINE: GNUM: G72-100MI-JMPB-AAA
R17 = RESC0402: Resistor,Chip;1.00mm L X 0.5mm W X 0.35mm H; Manufacturer #1: Generic; Part Number: TBD; Also Known As: 0402; PCBL.Component: CHP;RESC;1500;1700;150;400;700;950;600; PCBL.Process: F;N;50;50;200;100;200;250;350;-50;0; Tolerance: 5%; GNUM: G11-R0402-1002-AAA; POPOP: OMIT
R26 = RESC0603: as R20 on sheet ICDI
R27 = RESC0402: as R3 on sheet IO
R28 = RESC0402: as R18 on sheet ICDI
R30 = RESC0603: GNUM: G11-R0603-R000-AAA
R31 = RESC0402: Resistor,Chip;1.00mm L X 0.5mm W X 0.35mm H; Manufacturer #1: Generic; Part Number: TBD; Also Known As: 0402; PCBL.Component: CHP;RESC;1500;1700;150;400;700;950;600; PCBL.Process: F;N;50;50;200;100;200;250;350;-50;0; Tolerance: 5%; GNUM: G11-R0402-1004-AAA
RESET = SW-EVQQ2: as SW1 on sheet IO
SW3 = SW_DPDT: Geometry.Height: 50.00mil; GNUM: G21-SMGUL-DPDT-AAA
U1 = TM4C123G: GNUM: G50-QFP64-F120-EGC
U4 = TLV803: GNUM: G57-TIDBV-803M-AAA; POPOP: OMIT
U8 = TPS73633DRB: GNUM: G51-SON08-T633-AAA
Y1 = XTAL-NX5032GA: GNUM: G15-AB26T-3272-AAA; P/N: AB26TR
Y2 = XTAL-NX5032GA: as Y5 on sheet ICDI

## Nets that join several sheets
+3.3V: ICDI (16 pins), IO (J1.1), POWER (6 pins)
+ICDI_VBUS: ICDI (J11.1 R24.2), POWER (H19.1 SW3.3 SW3.4)
+MCU_PWR: ICDI (R18.1 R23.1), POWER (16 pins)
+USB_VBUS: IO (J9.1 R29.1), POWER (H18.1 SW3.1 SW3.6)
+VBUS: IO (D1.1 J3.1), POWER (8 pins)
GND: ICDI (26 pins), IO (11 pins), POWER (30 pins)
TARGETRS~{T}: ICDI (U2.23), IO (J2.5), POWER (7 pins)
~{WAKE}: IO (R8.1), POWER (H21.1 R31.2 U1.32)
ICDI~{_}RS~{T}: ICDI (C34.1 J5.10 R19.2 U2.38), POWER (D2.2)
